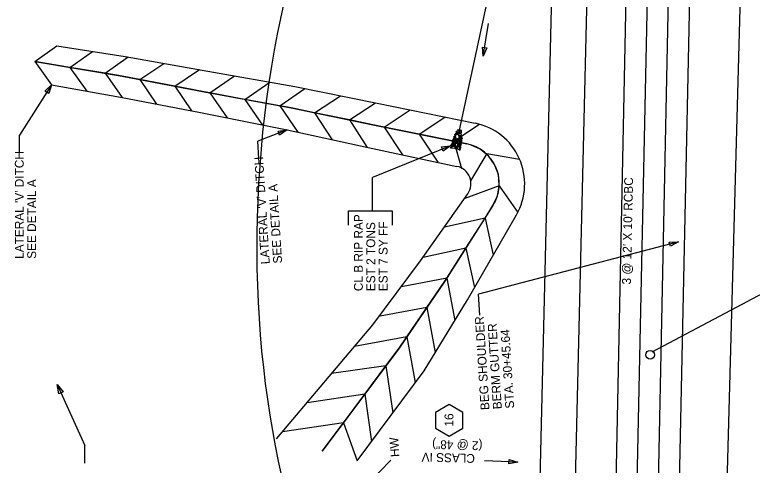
# Model space of a CAD drawing. Extents: x 2384780 to 2405432, y 547869 to 573706.
# Drawn here: x 2395364.1 to 2395781.4, y 553880.8 to 554135.3 of the extents above; entities that cross this region are included whole.
import ezdxf

# ---------------------------------------------------------------- set-up
doc = ezdxf.new("R2010")
doc.units = 0
for name, color, linetype in [('Old_Level_1', 7, 'Continuous'), ('Old_Level_10', 7, 'Continuous'), ('Old_Level_23', 7, 'Continuous'), ('Old_Level_5', 7, 'Continuous'), ('Old_Level_63', 7, 'Continuous'), ('Prop Buffer Zone 1', 7, 'Continuous'), ('Prop Buffer Zone 2', 7, 'Continuous'), ('Prop Ditch Text', 7, 'Continuous'), ('Prop Drainage Box Number Symbol CELL', 7, 'Continuous'), ('Prop Drop Inlet Text', 7, 'Continuous'), ('Prop Lateral V Ditch Detail CELL', 7, 'Continuous'), ('Prop Rip Rap Class B', 7, 'Continuous'), ('Prop Rip Rap Class B Text', 7, 'Continuous')]:
    doc.layers.add(name, color=color, linetype=linetype)

msp = doc.modelspace()

# ---------------------------------------------------------------- linework, layer by layer
at = {"layer": 'Old_Level_1'}
msp.add_line((2395615.73, 554070.19), (2395636.99, 554168.34), dxfattribs=at)
at = {"layer": 'Old_Level_10'}
for p, q in [((2395711.7, 554229.79), (2395702.14, 553776.55)), ((2395723.64, 554226.88), (2395714.42, 553789.9)), ((2395735.58, 554224.05), (2395726.7, 553803.26)), ((2395747.52, 554221.18), (2395738.99, 553816.62))]:
    msp.add_line(p, q, dxfattribs=at)
at = {"layer": 'Old_Level_23'}
msp.add_circle((2395723.66, 553943.17), 2.5, dxfattribs=at)
at = {"layer": 'Old_Level_5'}
for p, q in [((2395629.1, 554111.84), (2395632.25, 554130.36)), ((2395739.6, 554007.04), (2395626.46, 553977.45)), ((2395627.33, 553965.54), (2395626.46, 553977.45)), ((2395562.08, 553868.52), (2395576.89, 553883.68)), ((2395648.74, 553882.58), (2395629.96, 553883.16))]:
    msp.add_line(p, q, dxfattribs=at)
for points in [[(2395631.17, 554116.56), (2395629.1, 554111.84), (2395628.71, 554116.98)], [(2395734.45, 554006.89), (2395739.6, 554007.04), (2395735.13, 554004.49)], [(2395643.78, 553883.98), (2395648.74, 553882.58), (2395643.7, 553881.49)]]:
    msp.add_lwpolyline(points, close=True, dxfattribs=at)
at = {"layer": 'Old_Level_63'}
msp.add_lwpolyline([(2395724.84, 553944.75), (2397412.66, 554838.04)], dxfattribs=at)
msp.add_ellipse((2395727.45, 554021.06), major_axis=(15.71, 376.73), ratio=0.598979, dxfattribs=at)
at = {"layer": 'Prop Buffer Zone 1'}
for points in [[(2395766.48, 553842.97), (2395775.08, 554159.7)], [(2395680.91, 553848.68), (2395688.2, 554154.55)]]:
    msp.add_lwpolyline(points, dxfattribs=at)
at = {"layer": 'Prop Buffer Zone 2'}
msp.add_lwpolyline([(2395660.91, 553849.16), (2395668.2, 554155.02)], dxfattribs=at)
at = {"layer": 'Prop Ditch Text'}
for p, q in [((2395384.98, 554095.7), (2395366.88, 554067.33)), ((2395366.88, 554057.33), (2395366.88, 554067.33)), ((2395518.24, 554070.22), (2395501.66, 554063.91)), ((2395502.27, 554054.17), (2395501.66, 554063.91)), ((2395388.18, 553926.42), (2395403.86, 553891.92)), ((2395403.86, 553881.92), (2395403.86, 553891.92))]:
    msp.add_line(p, q, dxfattribs=at)
for points in [[(2395381.23, 554092.16), (2395384.98, 554095.7), (2395383.34, 554090.81)], [(2395513.13, 554069.61), (2395518.24, 554070.22), (2395514.02, 554067.28)], [(2395389.14, 553921.17), (2395388.18, 553926.42), (2395391.5, 553922.19)]]:
    msp.add_lwpolyline(points, close=True, dxfattribs=at)
at = {"layer": 'Prop Drainage Box Number Symbol CELL'}
msp.add_lwpolyline([(2395609.94, 553897.22), (2395617.69, 553901.69), (2395617.69, 553910.64), (2395609.94, 553915.12), (2395602.19, 553910.64), (2395602.19, 553901.69)], close=True, dxfattribs=at)
at = {"layer": 'Prop Lateral V Ditch Detail CELL'}
for p, q in [((2395375.57, 554108.95), (2395387.91, 554117.71)), ((2395395.39, 554105.59), (2395408.06, 554114.58)), ((2395375.57, 554108.95), (2395384.98, 554095.7)), ((2395415.22, 554102.22), (2395428.22, 554111.45)), ((2395395.39, 554105.59), (2395404.92, 554092.17)), ((2395435, 554098.66), (2395448.5, 554107.84)), ((2395454.75, 554094.89), (2395468.58, 554104.29)), ((2395415.22, 554102.22), (2395424.86, 554088.64)), ((2395474.51, 554091.15), (2395488.49, 554100.79)), ((2395435, 554098.66), (2395444.4, 554084.83)), ((2395494.28, 554087.51), (2395508.45, 554097.28)), ((2395454.75, 554094.89), (2395464.21, 554080.98)), ((2395514.05, 554083.87), (2395528.23, 554093.64)), ((2395474.51, 554091.15), (2395484.25, 554077.01)), ((2395494.28, 554087.51), (2395504.27, 554073.01)), ((2395533.77, 554079.94), (2395548.39, 554089.54)), ((2395514.05, 554083.87), (2395524.38, 554068.89)), ((2395553.46, 554075.86), (2395568.16, 554085.51)), ((2395569.12, 554085.31), (2395624.64, 554074.05)), ((2395533.77, 554079.94), (2395543.79, 554064.68)), ((2395573.15, 554071.81), (2395587.77, 554081.53)), ((2395553.46, 554075.86), (2395563.62, 554060.38)), ((2395592.86, 554067.84), (2395607.44, 554077.54)), ((2395566.65, 554073.12), (2395619.86, 554062.41)), ((2395573.15, 554071.81), (2395583.56, 554056.16)), ((2395612.57, 554063.88), (2395627.02, 554073.48)), ((2395592.86, 554067.84), (2395603.42, 554051.96)), ((2395612.57, 554063.88), (2395616.9, 554048.38)), ((2395564.04, 554060.29), (2395614.32, 554049.66)), ((2395631.21, 554056.84), (2395622.03, 554041.39)), ((2395631.21, 554056.84), (2395649.75, 554053.75)), ((2395638.23, 554038.56), (2395618.71, 554031.45)), ((2395638.23, 554038.56), (2395648.77, 554023.61)), ((2395593.79, 553996.21), (2395620.43, 554034.12)), ((2395630.21, 554020.42), (2395607.22, 554015.32)), ((2395630.21, 554020.42), (2395634.85, 553999.48)), ((2395619.4, 554003.46), (2395595.2, 553998.09)), ((2395619.4, 554003.46), (2395624.33, 553981.25)), ((2395608.66, 553986.47), (2395582.89, 553981.66)), ((2395608.66, 553986.47), (2395613.12, 553962.56)), ((2395597.29, 553969.88), (2395570.85, 553964.95)), ((2395597.29, 553969.88), (2395602.03, 553944.48)), ((2395585.92, 553953.3), (2395556.32, 553947.78)), ((2395585.92, 553953.3), (2395590.73, 553927.49)), ((2395574.15, 553937), (2395543.39, 553932.51)), ((2395574.15, 553937), (2395578.04, 553910.41)), ((2395562.14, 553920.88), (2395529.52, 553916.11)), ((2395562.14, 553920.88), (2395566.03, 553894.26)), ((2395550.13, 553904.76), (2395515.64, 553899.72)), ((2395550.13, 553904.76), (2395557.84, 553883.24))]:
    msp.add_line(p, q, dxfattribs=at)
for points in [[(2395387.91, 554117.71), (2395426.53, 554111.71), (2395473.32, 554103.45), (2395522.56, 554094.79), (2395569.12, 554085.31)], [(2395375.57, 554108.95), (2395424.88, 554100.59), (2395471.26, 554091.75), (2395520.44, 554082.7), (2395566.65, 554073.12)], [(2395538.12, 553888.63), (2395550.13, 553904.76), (2395562.14, 553920.88), (2395574.15, 553937), (2395581.55, 553946.92), (2395585.92, 553953.3), (2395597.29, 553969.88), (2395607.51, 553984.79), (2395608.6, 553986.5), (2395619.4, 554003.46), (2395630.21, 554020.42), (2395634.72, 554027.5), (2395637.27, 554032.99), (2395638.23, 554038.56), (2395638.3, 554038.95), (2395637.74, 554044.98), (2395635.63, 554050.65), (2395632.11, 554055.58), (2395630.92, 554056.56), (2395627.43, 554059.41), (2395621.91, 554061.9), (2395619.86, 554062.41), (2395612.57, 554063.88), (2395592.86, 554067.84), (2395573.15, 554071.81), (2395566.65, 554073.12), (2395553.46, 554075.86), (2395533.77, 554079.94), (2395520.44, 554082.7), (2395514.05, 554083.87), (2395494.28, 554087.51), (2395474.51, 554091.15), (2395471.26, 554091.75), (2395454.75, 554094.89), (2395435, 554098.66), (2395424.88, 554100.59), (2395415.22, 554102.22), (2395395.39, 554105.59), (2395375.57, 554108.95)], [(2395384.98, 554095.7), (2395424, 554088.79), (2395469.2, 554080.01), (2395518.24, 554070.22), (2395564.04, 554060.29)], [(2395634.72, 554027.5), (2395607.51, 553984.79), (2395581.55, 553946.92), (2395538.12, 553888.63)], [(2395557.84, 553883.24), (2395595.71, 553934.18), (2395620.25, 553974.18), (2395647.99, 554022.25)], [(2395512.25, 553895.7), (2395566.81, 553960.17), (2395593.79, 553996.21)]]:
    msp.add_lwpolyline(points, dxfattribs=at)
for centre, radius, start, end in [((2395617.67, 554039.75), 35, 330.0144, 78.5271), ((2395615.32, 554039.86), 23, 327.4997, 78.6131), ((2395612.25, 554039.87), 10, 324.902, 78.0608)]:
    msp.add_arc(centre, radius, start, end, dxfattribs=at)
at = {"layer": 'Prop Rip Rap Class B'}
for points in [[(2395613.34, 554066.96), (2395613.18, 554067.22), (2395613.15, 554067.72), (2395613.38, 554067.9), (2395613.6, 554067.86), (2395613.68, 554067.21), (2395613.54, 554067.03), (2395613.34, 554066.96)], [(2395614.72, 554064.52), (2395614.12, 554065.13), (2395613.35, 554066.69), (2395614.05, 554067.67), (2395614.87, 554067.77), (2395615.87, 554065.86), (2395615.59, 554064.92), (2395614.81, 554064.38)], [(2395613.77, 554067.54), (2395613.58, 554067.75), (2395613.55, 554068.25), (2395613.81, 554068.43), (2395614, 554068.39), (2395614.11, 554067.78), (2395613.96, 554067.57), (2395613.77, 554067.54)], [(2395613.93, 554069.45), (2395614.36, 554069.56), (2395615.38, 554069.69), (2395615.82, 554069.13), (2395615.68, 554068.6), (2395614.45, 554068.52), (2395613.94, 554068.91), (2395613.91, 554069.33)], [(2395614.11, 554068.5), (2395614.33, 554068.47), (2395614.77, 554068.4), (2395614.84, 554068.08), (2395614.8, 554067.9), (2395614.21, 554068), (2395613.96, 554068.26), (2395614.11, 554068.5)], [(2395615.67, 554069.89), (2395615.45, 554069.86), (2395614.93, 554069.72), (2395614.78, 554070.04), (2395614.82, 554070.22), (2395615.46, 554070.39), (2395615.73, 554070.19), (2395615.67, 554069.89)], [(2395614.99, 554068.35), (2395615.5, 554068.39), (2395616.5, 554068.22), (2395616.72, 554067.49), (2395616.46, 554067.12), (2395615.26, 554067.4), (2395614.93, 554067.88), (2395614.99, 554068.35)], [(2395615.57, 554066.45), (2395615.38, 554066.66), (2395615.36, 554067.16), (2395615.6, 554067.36), (2395615.78, 554067.29), (2395615.88, 554066.69), (2395615.77, 554066.52), (2395615.57, 554066.45)], [(2395616.7, 554069.85), (2395616.46, 554069.8), (2395615.9, 554069.67), (2395615.81, 554069.99), (2395615.83, 554070.18), (2395616.43, 554070.32), (2395616.74, 554070.14), (2395616.7, 554069.85)], [(2395616.08, 554068.32), (2395615.96, 554068.65), (2395615.83, 554069.27), (2395616.25, 554069.63), (2395616.64, 554069.56), (2395616.68, 554068.64), (2395616.44, 554068.38), (2395616.08, 554068.32)], [(2395616.05, 554066.1), (2395615.87, 554066.37), (2395615.89, 554066.85), (2395616.1, 554067.05), (2395616.32, 554067), (2395616.4, 554066.34), (2395616.25, 554066.18), (2395616.05, 554066.1)], [(2395616.64, 554066.13), (2395616.44, 554066.34), (2395616.42, 554066.84), (2395616.67, 554067.04), (2395616.85, 554066.96), (2395616.94, 554066.37), (2395616.84, 554066.2), (2395616.64, 554066.13)], [(2395611.72, 554062.02), (2395611.57, 554062.32), (2395611.52, 554062.83), (2395611.78, 554062.97), (2395611.95, 554062.93), (2395612.08, 554062.3), (2395611.93, 554062.1), (2395611.72, 554062.02)], [(2395611.98, 554063.37), (2395611.79, 554063.59), (2395611.76, 554064.09), (2395612.03, 554064.27), (2395612.21, 554064.23), (2395612.33, 554063.61), (2395612.18, 554063.41), (2395611.98, 554063.37)], [(2395612.8, 554062.91), (2395612.57, 554062.88), (2395612.07, 554062.86), (2395611.89, 554063.11), (2395611.91, 554063.26), (2395612.43, 554063.4), (2395612.71, 554063.23), (2395612.78, 554063.03)], [(2395612.36, 554064.34), (2395612.17, 554064.56), (2395612.14, 554065.06), (2395612.41, 554065.24), (2395612.59, 554065.2), (2395612.71, 554064.58), (2395612.56, 554064.38), (2395612.36, 554064.34)], [(2395612.42, 554061.86), (2395612.38, 554062.06), (2395612.26, 554062.58), (2395612.6, 554062.76), (2395612.79, 554062.72), (2395612.9, 554062.05), (2395612.66, 554061.93), (2395612.42, 554061.86)], [(2395612.52, 554064.29), (2395613.05, 554064.3), (2395614.03, 554064.03), (2395614.22, 554063.39), (2395613.97, 554062.9), (2395612.8, 554063.2), (2395612.37, 554063.78), (2395612.52, 554064.29)], [(2395612.64, 554066.45), (2395612.95, 554066.48), (2395613.44, 554066.44), (2395613.49, 554066.09), (2395613.38, 554065.84), (2395612.76, 554066.02), (2395612.58, 554066.28), (2395612.64, 554066.45)], [(2395612.6, 554065.58), (2395612.92, 554065.75), (2395613.63, 554065.83), (2395613.9, 554065.47), (2395613.85, 554065.18), (2395612.99, 554065.01), (2395612.64, 554065.27), (2395612.6, 554065.58)], [(2395613.57, 554064.53), (2395613.34, 554064.46), (2395612.82, 554064.34), (2395612.68, 554064.7), (2395612.71, 554064.86), (2395613.35, 554064.98), (2395613.51, 554064.85), (2395613.57, 554064.53)], [(2395613.16, 554062.05), (2395612.97, 554062.3), (2395612.95, 554062.8), (2395613.22, 554062.98), (2395613.4, 554062.92), (2395613.49, 554062.33), (2395613.37, 554062.12), (2395613.16, 554062.05)], [(2395614.44, 554062.77), (2395614.55, 554062.34), (2395614.67, 554061.29), (2395614.11, 554060.9), (2395613.6, 554060.99), (2395613.54, 554062.21), (2395613.79, 554062.78), (2395614.32, 554062.76)], [(2395613.88, 554064.22), (2395613.69, 554064.42), (2395613.7, 554064.93), (2395613.91, 554065.11), (2395614.13, 554065.07), (2395614.23, 554064.45), (2395614.07, 554064.25), (2395613.88, 554064.22)], [(2395616.46, 554062.89), (2395615.95, 554062.71), (2395614.79, 554062.45), (2395614.29, 554063.26), (2395614.37, 554063.74), (2395615.84, 554063.91), (2395616.49, 554063.51), (2395616.58, 554062.88)], [(2395614.43, 554064.44), (2395614.75, 554064.51), (2395615.13, 554064.33), (2395615.27, 554063.96), (2395615.12, 554063.8), (2395614.53, 554063.9), (2395614.39, 554064.26), (2395614.43, 554064.44)], [(2395614.98, 554061.48), (2395614.82, 554061.68), (2395614.75, 554062.24), (2395615.02, 554062.42), (2395615.2, 554062.35), (2395615.32, 554061.72), (2395615.22, 554061.55), (2395614.98, 554061.48)], [(2395615.36, 554062.34), (2395615.68, 554062.4), (2395616.06, 554062.23), (2395616.2, 554061.86), (2395616.05, 554061.7), (2395615.46, 554061.8), (2395615.32, 554062.15), (2395615.36, 554062.34)], [(2395615.8, 554064.07), (2395615.64, 554064.3), (2395615.64, 554064.78), (2395615.87, 554064.98), (2395616.09, 554064.93), (2395616.15, 554064.31), (2395616, 554064.15), (2395615.8, 554064.07)], [(2395616.07, 554066.07), (2395616.48, 554066.12), (2395617.08, 554066.02), (2395617.21, 554065.47), (2395617.01, 554065.19), (2395616.17, 554065.43), (2395616.01, 554065.79), (2395616.07, 554066.07)], [(2395617.05, 554063.86), (2395616.83, 554063.71), (2395616.4, 554063.66), (2395616.15, 554063.91), (2395616.2, 554064.23), (2395616.8, 554064.2), (2395617.08, 554064.04), (2395617.05, 554063.86)], [(2395616.4, 554061.82), (2395616.2, 554062.04), (2395616.19, 554062.54), (2395616.43, 554062.73), (2395616.61, 554062.66), (2395616.71, 554062.08), (2395616.61, 554061.91), (2395616.4, 554061.82)], [(2395616.6, 554064.22), (2395616.42, 554064.45), (2395616.4, 554064.95), (2395616.64, 554065.13), (2395616.82, 554065.06), (2395616.92, 554064.48), (2395616.81, 554064.31), (2395616.6, 554064.22)], [(2395610.68, 554060.4), (2395610.99, 554060.43), (2395611.48, 554060.39), (2395611.53, 554060.04), (2395611.42, 554059.79), (2395610.8, 554059.97), (2395610.62, 554060.22), (2395610.68, 554060.4)], [(2395610.71, 554061.42), (2395611.02, 554061.45), (2395611.51, 554061.4), (2395611.56, 554061.05), (2395611.45, 554060.8), (2395610.83, 554060.99), (2395610.65, 554061.24), (2395610.71, 554061.42)], [(2395611.14, 554061.96), (2395611.45, 554062), (2395611.94, 554061.96), (2395611.98, 554061.6), (2395611.87, 554061.36), (2395611.26, 554061.54), (2395611.08, 554061.79), (2395611.14, 554061.96)], [(2395611.47, 554061), (2395611.99, 554060.99), (2395612.96, 554060.85), (2395613.18, 554060.1), (2395612.88, 554059.66), (2395611.71, 554059.94), (2395611.39, 554060.48), (2395611.47, 554061)], [(2395613.47, 554061.11), (2395613.1, 554060.99), (2395612.37, 554060.99), (2395612.14, 554061.34), (2395612.19, 554061.64), (2395613.04, 554061.72), (2395613.39, 554061.55), (2395613.47, 554061.11)], [(2395613.33, 554060.27), (2395613.7, 554060.28), (2395614.33, 554060.17), (2395614.44, 554059.61), (2395614.31, 554059.35), (2395613.41, 554059.61), (2395613.23, 554059.95), (2395613.33, 554060.27)], [(2395614.21, 554060.13), (2395614.02, 554060.36), (2395613.98, 554060.86), (2395614.24, 554061.04), (2395614.43, 554061), (2395614.55, 554060.37), (2395614.41, 554060.17), (2395614.21, 554060.13)], [(2395615.39, 554061.06), (2395615.62, 554060.61), (2395615.76, 554059.59), (2395615.19, 554059.15), (2395614.69, 554059.36), (2395614.59, 554060.59), (2395614.86, 554061), (2395615.41, 554061.13)], [(2395616.6, 554061.16), (2395616.29, 554060.99), (2395615.85, 554060.98), (2395615.61, 554061.21), (2395615.66, 554061.5), (2395616.26, 554061.48), (2395616.54, 554061.36), (2395616.6, 554061.16)], [(2395615.83, 554058.78), (2395615.63, 554059), (2395615.61, 554059.5), (2395615.87, 554059.69), (2395616.04, 554059.62), (2395616.15, 554059.04), (2395616.04, 554058.87), (2395615.83, 554058.78)], [(2395615.68, 554060.58), (2395616, 554060.64), (2395616.38, 554060.46), (2395616.5, 554060.09), (2395616.36, 554059.93), (2395615.77, 554060.03), (2395615.65, 554060.4), (2395615.68, 554060.58)]]:
    msp.add_lwpolyline(points, dxfattribs=at)
at = {"layer": 'Prop Rip Rap Class B Text'}
for p in [(2395610.66, 554061.26), (2395566.61, 554024.43)]:
    msp.add_line(p, (2395566.61, 554043.36), dxfattribs=at)
msp.add_lwpolyline([(2395605.55, 554060.62), (2395610.66, 554061.26), (2395606.45, 554058.29)], close=True, dxfattribs=at)
msp.add_lwpolyline([(2395552.92, 554016.45), (2395552.92, 554024.43), (2395577.73, 554024.43), (2395577.73, 554016.45)], dxfattribs=at)

# ---------------------------------------------------------------- texts
at = {"layer": 'Old_Level_1'}
for s, rotation, p in [("3 @ 12' X 10' RCBC", 88.7915, (2395712.72, 553982.84)), ('HW', 93.5443, (2395581.8, 553885.55)), ('(2 @ 48")', 178.4425, (2395628.82, 553894.23)), ('CLASS IV', 178.4425, (2395624.56, 553887.05))]:
    msp.add_text(s, height=5, rotation=rotation, dxfattribs=at).set_placement(p)
at = {"layer": 'Old_Level_5'}
for s, p in [('BEG SHOULDER', (2395632.77, 553912.1)), ('BERM GUTTER', (2395639.75, 553912.54)), ('STA. 30+45.64 ', (2395646.74, 553912.97))]:
    msp.add_text(s, height=5, rotation=93.5936, dxfattribs=at).set_placement(p)
at = {"layer": 'Prop Ditch Text'}
for s, rotation, p in [("LATERAL 'V' DITCH", 90, (2395369.22, 553997.39)), ("LATERAL 'V' DITCH", 93.5936, (2395508.44, 553994.49)), ('SEE DETAIL A', 90, (2395376.22, 553997.39)), ('SEE DETAIL A', 93.5936, (2395515.42, 553994.93))]:
    msp.add_text(s, height=5, rotation=rotation, dxfattribs=at).set_placement(p)
at = {"layer": 'Prop Drop Inlet Text'}
msp.add_text('16', height=5, rotation=90, dxfattribs=at).set_placement((2395612.32, 553902.6))
at = {"layer": 'Prop Rip Rap Class B Text'}
for s, p in [('CL B RIP RAP ', (2395561.06, 553979.12)), ('EST 2 TONS', (2395568.06, 553979.12)), ('EST 7 SY FF', (2395575.06, 553979.12))]:
    msp.add_text(s, height=5, rotation=90, dxfattribs=at).set_placement(p)

doc.saveas('drawing.dxf')
